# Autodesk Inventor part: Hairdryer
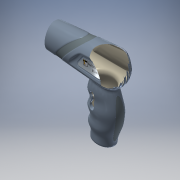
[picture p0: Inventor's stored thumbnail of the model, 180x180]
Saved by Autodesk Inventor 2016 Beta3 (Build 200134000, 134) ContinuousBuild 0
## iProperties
Created: 2005-09
Part Number: Hairdryer
Document SubType Name: Modeling
Designer: Autodesk, Inc.
Density: 1 g/cm^3
Mass: 22.9398 g
Surface Area: 393.919 cm^2
Volume: 22.9398 cm^3
Material: Generic
Appearance: Steel Blue
Author: Autodesk, Inc.
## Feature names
1. Body [Extrusion]
2. Body rear
3. Handle
4. Button_Recess [Extrusion]
5. Fillet26
6. Stripe
7. Indent Mirror [Mirror]
8. Indent Fillet 1 [Fillet]
9. Indent Fillet 2 [Fillet]
10. Fillet18
11. Fillet14
12. Shell8
13. Vents [Extrusion]
14. Interface [Extrusion]
15. Fillet16
16. Fillet15
17. Handle_Pad [Extrusion]
18. Fillet28
19. Mirror3
20. Fillet39
## Parameters: d15 = 31.75 mm, d17 = 31.75 mm, d52 = -5 mm, d85 = 15 mm, d261 = 3 mm, d271 = 4 deg, d274 = 12 mm, d275 = 1.2 mm, d321 = 2.2 mm, d328 = -4 deg, d334 = 0, d335 = 4 mm, d336 = 6 mm, d337 = 1.2 mm, d339 = 0, d345 = 90 deg, d347 = 90 deg, d349 = 0, d351 = 6 mm, d353 = 4 mm, d355 = 0, d356 = 4 mm, d357 = 5 mm, d358 = 0.25 mm, d379 = 4 mm, d381 = 13 mm, d383 = 5 mm, d384 = 25 mm, d389 = 8.5 mm, d411 = 5 deg, d412 = 0.5 mm, d417 = 0.3 mm, d418 = 0.5 mm, d419 = 28.575 mm, d421 = 0, d423 = 58 mm, d424 = 0.1 mm, d441 = 70.77 mm, d442 = -40 deg, d451 = 114 mm, d455 = 16 mm, d456 = 90 deg, d459 = 90 deg, d469 = 1.9 mm, d470 = 1.9 mm, d472 = 1.9 mm, d473 = 0.5 mm, d474 = 0.25 mm, d475 = 0, d480 = 7.777 mm, d488 = 6 mm, d489 = 3 mm, d490 = 13 mm, d491 = 17 mm, d492 = 19 mm, d493 = 7 mm, d494 = 11.5 mm, d495 = 14 mm, d501 = 3 deg, d502 = 3.5 deg, d503 = 1 mm, d522 = 1.5 mm, d539 = 0.5 mm, d666 = 0, d667 = 0
